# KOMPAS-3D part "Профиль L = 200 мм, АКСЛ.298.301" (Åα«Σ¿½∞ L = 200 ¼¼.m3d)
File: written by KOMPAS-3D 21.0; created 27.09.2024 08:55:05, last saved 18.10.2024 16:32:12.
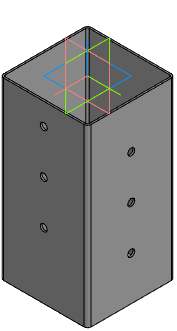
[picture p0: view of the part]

Document properties: Полное имя файла: C:\Users\Алексей Бочаров\YandexDisk\Соединения бруса\Соединения бруса\ТРИО\Профиль L = 200 мм.m3d; Автор: Алексей Бочаров

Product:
- Part/product: Профиль L = 200 мм  | designation АКСЛ.298.301
    Масса: 1.210897
    Форматы листов документа: A2

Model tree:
1. Эскиз:1
2. Элемент выдавливания:1
     Расстояние 2 = 200
3. Эскиз:2  (with: Элемент выдавливания:1)
4. Элемент выдавливания:2  (with: Элемент выдавливания:1)
     Расстояние 2 = 2
5. Эскиз:3  (with: Элемент выдавливания:1)
6. Элемент выдавливания:3  (with: Элемент выдавливания:1)
     Расстояние 2 = 2

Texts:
  АКСЛ.298.301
